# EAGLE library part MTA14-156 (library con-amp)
AMP connector
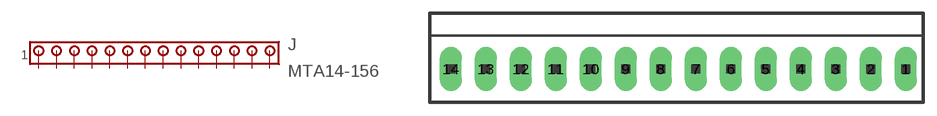
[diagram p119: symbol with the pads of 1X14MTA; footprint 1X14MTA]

Designator prefix J

## MTA14-156 (OC_FARNELL: unknown; OC_NEWARK: unknown)  [1X14MTA]
1  1  pas
2  2  pas
3  3  pas
4  4  pas
5  5  pas
6  6  pas
7  7  pas
8  8  pas
9  9  pas
10  10  pas
11  11  pas
12  12  pas
13  13  pas
14  14  pas

## Footprint 1X14MTA (pad centres in mm)
AMP MTA connector
drill 1.676 long: 1 25.756,0; 2 21.793,0; 3 17.831,0; 4 13.868,0; 5 9.906,0; 6 5.944,0; 7 1.981,0; 8 -1.981,0; 9 -5.944,0; 10 -9.906,0; 11 -13.868,0; 12 -17.831,0; 13 -21.793,0; 14 -25.756,0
